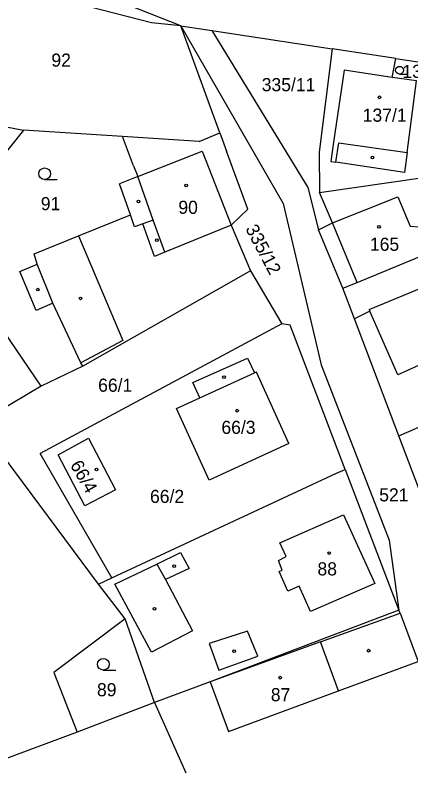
# Model space of a CAD drawing. Extents: x -762263 to -760336, y -1154405 to -1152076.
# Drawn here: x -761538.5 to -761487.2, y -1152449.2 to -1152351.2 of the extents above; entities that cross this region are included whole.
import ezdxf

# ---------------------------------------------------------------- set-up
doc = ezdxf.new("R2010")
doc.units = 0
for name, color, linetype in [('Vrstva 1', 7, 'Continuous'), ('Vrstva 17', 7, 'Continuous'), ('Vrstva 18', 7, 'Continuous'), ('Vrstva 19', 7, 'Continuous'), ('Vrstva 25', 7, 'Continuous'), ('Vrstva 4', 7, 'Continuous'), ('Vrstva 6', 7, 'Continuous')]:
    doc.layers.add(name, color=color, linetype=linetype)

msp = doc.modelspace()

# ---------------------------------------------------------------- linework, layer by layer
at = {"layer": 'Vrstva 1'}
for p, q in [((-761517.01, -1152352.57), (-761550.89, -1152339.13)), ((-761520.81, -1152352.15), (-761538.46, -1152347.62)), ((-761517.01, -1152352.57), (-761520.81, -1152352.15)), ((-761511.96, -1152366.43), (-761517.01, -1152352.57)), ((-761517.01, -1152352.57), (-761513.01, -1152353.18)), ((-761513.01, -1152353.18), (-761497.41, -1152355.55)), ((-761497.41, -1152355.55), (-761499.09, -1152368.91)), ((-761489.17, -1152356.81), (-761497.41, -1152355.55)), ((-761489.64, -1152359.26), (-761489.17, -1152356.81)), ((-761489.17, -1152356.81), (-761482.45, -1152357.83)), ((-761486.48, -1152359.67), (-761489.64, -1152359.26)), ((-761554.27, -1152362.87), (-761537.42, -1152366.06)), ((-761537.42, -1152366.06), (-761548.34, -1152379.84)), ((-761524.6, -1152366.89), (-761537.42, -1152366.06)), ((-761514.64, -1152367.53), (-761524.6, -1152366.89)), ((-761523.15, -1152370.7), (-761524.6, -1152366.89)), ((-761514.64, -1152367.53), (-761511.96, -1152366.43)), ((-761511.96, -1152366.43), (-761511.12, -1152368.8)), ((-761508.33, -1152376.32), (-761511.12, -1152368.8)), ((-761499.09, -1152368.91), (-761499.05, -1152374.15)), ((-761523.15, -1152370.7), (-761522.6, -1152372.09)), ((-761522.6, -1152372.09), (-761524.99, -1152373.03)), ((-761523.56, -1152377.05), (-761524.99, -1152373.03)), ((-761499.05, -1152374.15), (-761485.59, -1152372.21)), ((-761497.37, -1152378.07), (-761499.05, -1152374.15)), ((-761530.27, -1152379.77), (-761523.56, -1152377.05)), ((-761510.49, -1152378.4), (-761508.33, -1152376.32)), ((-761499.2, -1152379.01), (-761497.37, -1152378.07)), ((-761510.49, -1152378.4), (-761508.02, -1152384.31)), ((-761496.03, -1152386.53), (-761499.2, -1152379.01)), ((-761535.14, -1152399.26), (-761548.34, -1152379.84)), ((-761536.03, -1152382.11), (-761530.27, -1152379.77)), ((-761494.18, -1152385.8), (-761481.06, -1152380.35)), ((-761535.63, -1152383.42), (-761536.03, -1152382.11)), ((-761537.88, -1152384.37), (-761535.63, -1152383.42)), ((-761535.75, -1152389.44), (-761537.88, -1152384.37)), ((-761508.02, -1152384.31), (-761529.73, -1152396.67)), ((-761508.02, -1152384.31), (-761503.93, -1152391.16)), ((-761496.03, -1152386.53), (-761494.18, -1152385.8)), ((-761494.52, -1152390.53), (-761496.03, -1152386.53)), ((-761533.6, -1152388.51), (-761535.75, -1152389.44)), ((-761529.98, -1152396.23), (-761533.6, -1152388.51)), ((-761488.79, -1152405.68), (-761448.12, -1152388.13)), ((-761492.53, -1152389.53), (-761494.52, -1152390.53)), ((-761488.94, -1152397.76), (-761492.53, -1152389.53)), ((-761488.79, -1152405.68), (-761494.52, -1152390.53)), ((-761503.93, -1152391.16), (-761535.26, -1152407.99)), ((-761502.86, -1152391.35), (-761503.93, -1152391.16)), ((-761495.76, -1152410.04), (-761502.86, -1152391.35)), ((-761480.73, -1152394.13), (-761488.94, -1152397.76)), ((-761515.49, -1152398.77), (-761508.39, -1152395.6)), ((-761508.39, -1152395.6), (-761507.5, -1152397.54)), ((-761529.73, -1152396.67), (-761535.14, -1152399.26)), ((-761529.73, -1152396.67), (-761529.98, -1152396.23)), ((-761507.23, -1152397.42), (-761507.5, -1152397.54)), ((-761503.06, -1152406.68), (-761507.23, -1152397.42)), ((-761535.14, -1152399.26), (-761543.2, -1152404.05)), ((-761514.57, -1152400.76), (-761515.49, -1152398.77)), ((-761517.6, -1152402.14), (-761514.57, -1152400.76)), ((-761513.38, -1152411.43), (-761517.6, -1152402.14)), ((-761527.68, -1152424.89), (-761543.2, -1152404.05)), ((-761532.92, -1152408.16), (-761528.97, -1152406)), ((-761528.97, -1152406), (-761525.49, -1152412.67)), ((-761484.44, -1152417.22), (-761488.79, -1152405.68)), ((-761503.06, -1152406.68), (-761513.38, -1152411.43)), ((-761525.98, -1152424.09), (-761535.26, -1152407.99)), ((-761529.47, -1152414.75), (-761532.92, -1152408.16)), ((-761496.87, -1152410.51), (-761495.76, -1152410.04)), ((-761495.76, -1152410.04), (-761488.77, -1152428.26)), ((-761525.98, -1152424.09), (-761496.87, -1152410.51)), ((-761525.49, -1152412.67), (-761529.47, -1152414.75)), ((-761527.68, -1152424.89), (-761525.98, -1152424.09)), ((-761524.24, -1152429.4), (-761527.68, -1152424.89)), ((-761488.77, -1152428.26), (-761513.24, -1152437.58)), ((-761488.62, -1152428.65), (-761488.77, -1152428.26)), ((-761488.62, -1152428.65), (-761486.29, -1152434.93)), ((-761524.24, -1152429.4), (-761533.5, -1152436.34)), ((-761520.46, -1152440.25), (-761524.24, -1152429.4)), ((-761533.5, -1152436.34), (-761530.48, -1152444.07)), ((-761513.24, -1152437.58), (-761520.46, -1152440.25)), ((-761520.46, -1152440.25), (-761530.48, -1152444.07)), ((-761520.46, -1152440.25), (-761516.38, -1152449.36)), ((-761530.48, -1152444.07), (-761561.5, -1152455.64))]:
    msp.add_line(p, q, dxfattribs=at)
at = {"layer": 'Vrstva 25'}
for p, q in [((-761488.7, -1152358.81), (-761487.628, -1152358.81)), ((-761534.67, -1152372.47), (-761533.07, -1152372.47)), ((-761527.07, -1152436.04), (-761525.47, -1152436.04))]:
    msp.add_line(p, q, dxfattribs=at)
for centre, radius in [((-761488.7, -1152358.308), 0.503), ((-761491.3, -1152361.82), 0.175), ((-761492.22, -1152369.63), 0.175), ((-761534.67, -1152371.72), 0.75), ((-761516.35, -1152373.25), 0.175), ((-761522.51, -1152375.31), 0.175), ((-761491.36, -1152378.59), 0.175), ((-761520.15, -1152380.33), 0.175), ((-761535.56, -1152386.74), 0.175), ((-761530.01, -1152387.87), 0.175), ((-761511.44, -1152398.08), 0.175), ((-761509.72, -1152402.42), 0.175), ((-761527.96, -1152410.05), 0.175), ((-761497.82, -1152420.87), 0.175), ((-761517.9, -1152422.58), 0.175), ((-761520.44, -1152428.11), 0.175), ((-761510.11, -1152433.58), 0.175), ((-761492.7, -1152433.52), 0.175), ((-761527.07, -1152435.29), 0.75), ((-761504.17, -1152437.02), 0.175)]:
    msp.add_circle(centre, radius, dxfattribs=at)
at = {"layer": 'Vrstva 4'}
for p, q in [((-761495.89, -1152358.3), (-761497.25, -1152367.62)), ((-761489.64, -1152359.26), (-761495.89, -1152358.3)), ((-761487.69, -1152368.99), (-761486.48, -1152359.67)), ((-761497.25, -1152367.62), (-761497.62, -1152370.15)), ((-761496.95, -1152370.24), (-761496.58, -1152367.72)), ((-761496.58, -1152367.72), (-761487.69, -1152368.99)), ((-761522.6, -1152372.09), (-761514.26, -1152368.81)), ((-761514.26, -1152368.81), (-761510.49, -1152378.4)), ((-761487.69, -1152368.99), (-761488.07, -1152371.54)), ((-761497.62, -1152370.15), (-761496.95, -1152370.24)), ((-761488.07, -1152371.54), (-761496.95, -1152370.24)), ((-761520.6, -1152377.72), (-761522.6, -1152372.09)), ((-761497.37, -1152378.07), (-761488.9, -1152374.72)), ((-761488.9, -1152374.72), (-761487.33, -1152378.52)), ((-761523.02, -1152378.58), (-761523.56, -1152377.05)), ((-761520.6, -1152377.72), (-761521.96, -1152378.2)), ((-761519.11, -1152381.9), (-761520.6, -1152377.72)), ((-761494.18, -1152385.8), (-761497.37, -1152378.07)), ((-761521.96, -1152378.2), (-761523.02, -1152378.58)), ((-761520.45, -1152382.45), (-761521.96, -1152378.2)), ((-761510.49, -1152378.4), (-761519.11, -1152381.9)), ((-761487.33, -1152378.52), (-761486.23, -1152378.6)), ((-761530.27, -1152379.77), (-761524.53, -1152393.35)), ((-761519.11, -1152381.9), (-761520.45, -1152382.45)), ((-761533.6, -1152388.51), (-761535.63, -1152383.42)), ((-761492.63, -1152389.3), (-761484.23, -1152385.85)), ((-761492.63, -1152389.3), (-761492.53, -1152389.53)), ((-761524.53, -1152393.35), (-761529.98, -1152396.23)), ((-761514.57, -1152400.76), (-761507.5, -1152397.54)), ((-761504.21, -1152419.55), (-761495.97, -1152415.9)), ((-761495.97, -1152415.9), (-761491.92, -1152424.81)), ((-761503.4, -1152421.32), (-761504.21, -1152419.55)), ((-761520.16, -1152422.3), (-761517.07, -1152420.81)), ((-761517.07, -1152420.81), (-761515.93, -1152422.87)), ((-761504.38, -1152421.83), (-761503.4, -1152421.32)), ((-761503.9, -1152423.09), (-761504.38, -1152421.83)), ((-761525.57, -1152424.92), (-761520.16, -1152422.3)), ((-761520.16, -1152422.3), (-761519, -1152424.28)), ((-761515.93, -1152422.87), (-761519, -1152424.28)), ((-761504.28, -1152423.25), (-761503.9, -1152423.09)), ((-761503.18, -1152425.8), (-761504.28, -1152423.25)), ((-761520.83, -1152433.71), (-761525.57, -1152424.92)), ((-761519, -1152424.28), (-761515.54, -1152430.96)), ((-761491.92, -1152424.81), (-761500.22, -1152428.43)), ((-761501.72, -1152425.18), (-761503.18, -1152425.8)), ((-761500.22, -1152428.43), (-761501.72, -1152425.18)), ((-761498.92, -1152432.39), (-761488.62, -1152428.65)), ((-761515.54, -1152430.96), (-761520.83, -1152433.71)), ((-761508.39, -1152430.99), (-761513.35, -1152432.6)), ((-761507.06, -1152434.25), (-761508.39, -1152430.99)), ((-761513.35, -1152432.6), (-761512.1, -1152436.04)), ((-761498.92, -1152432.39), (-761513.24, -1152437.58)), ((-761496.62, -1152438.73), (-761498.92, -1152432.39)), ((-761512.1, -1152436.04), (-761507.06, -1152434.25)), ((-761496.62, -1152438.73), (-761486.29, -1152434.93)), ((-761513.24, -1152437.58), (-761510.86, -1152443.98)), ((-761510.86, -1152443.98), (-761496.62, -1152438.73))]:
    msp.add_line(p, q, dxfattribs=at)
at = {"layer": 'Vrstva 6'}
for p, q in [((-761517.01, -1152352.57), (-761503.78, -1152375.59)), ((-761513.01, -1152353.18), (-761500.57, -1152373.5)), ((-761500.57, -1152373.5), (-761499.2, -1152379.01)), ((-761503.78, -1152375.59), (-761498.87, -1152396.5)), ((-761498.87, -1152396.5), (-761490.05, -1152419.2)), ((-761490.05, -1152419.2), (-761488.77, -1152428.26))]:
    msp.add_line(p, q, dxfattribs=at)

# ---------------------------------------------------------------- texts
at = {"layer": 'Vrstva 17'}
msp.add_text('521', height=1.7, dxfattribs=at).set_placement((-761491.332, -1152414.18))
at = {"layer": 'Vrstva 18'}
for s, p in [('92', (-761533.799, -1152357.85)), ('136/2', (-761488.326, -1152359.31)), ('335/11', (-761506.557, -1152361.03)), ('91', (-761535.173, -1152376.45)), ('66/1', (-761527.743, -1152399.97)), ('66/2', (-761521.023, -1152414.38)), ('89', (-761527.893, -1152439.43))]:
    msp.add_text(s, height=1.7, dxfattribs=at).set_placement(p)
msp.add_text('335/12', height=1.7, rotation=297.82346, dxfattribs=at).set_placement((-761508.709, -1152378.841))
at = {"layer": 'Vrstva 19'}
for s, p in [('137/1', (-761493.467, -1152364.98)), ('90', (-761517.353, -1152376.92)), ('165', (-761492.537, -1152381.71)), ('66/3', (-761511.773, -1152405.43)), ('88', (-761499.332, -1152423.77)), ('87', (-761505.373, -1152440.07))]:
    msp.add_text(s, height=1.7, dxfattribs=at).set_placement(p)
msp.add_text('66/4', height=1.7, rotation=299.65693, dxfattribs=at).set_placement((-761531.423, -1152409.45))

doc.saveas('drawing.dxf')
